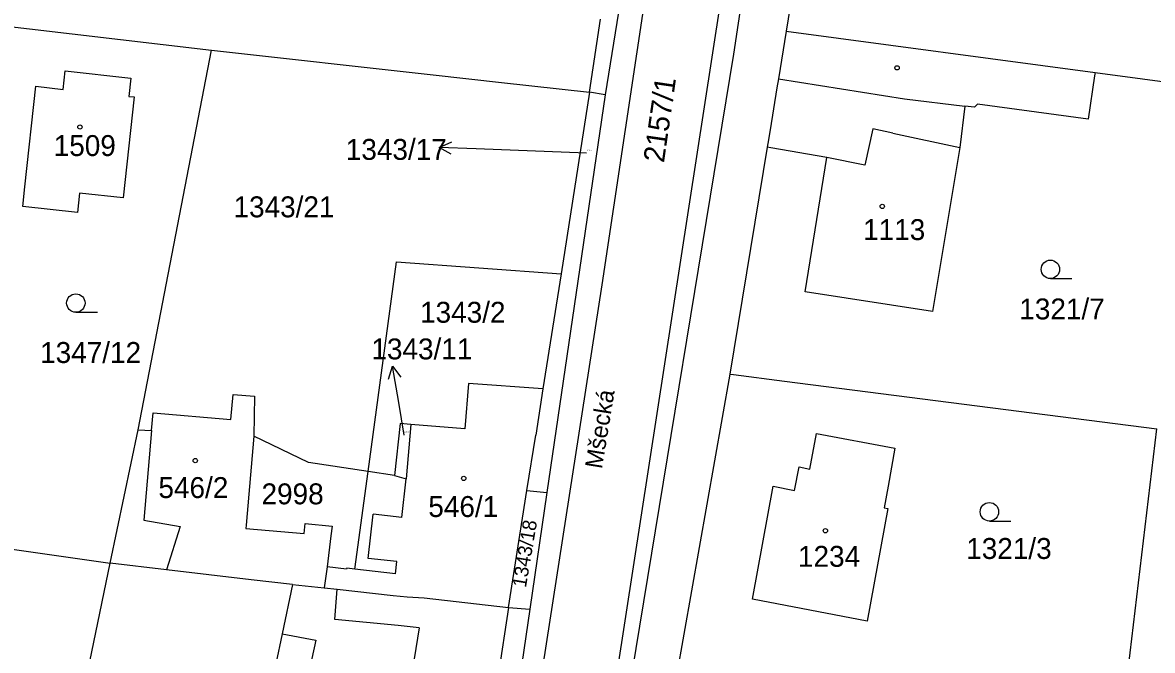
# Model space of a CAD drawing. Extents: x -779596 to -776743, y -1030330 to -1024513.
# Drawn here: x -778783.4 to -778691.5, y -1030030.7 to -1029979.6 of the extents above; entities that cross this region are included whole.
import ezdxf

# ---------------------------------------------------------------- set-up
doc = ezdxf.new("R2010")
doc.units = 0
for name, color, linetype in [('hranice parcel', 7, 'Continuous'), ('hranice vnitřní', 7, 'Continuous'), ('kultura', 7, 'Continuous'), ('názvosloví', 7, 'Continuous'), ('č_ parcel šipka', 7, 'Continuous'), ('č_pacel stav_', 7, 'Continuous'), ('č_parcel poz_', 7, 'Continuous')]:
    doc.layers.add(name, color=color, linetype=linetype)

msp = doc.modelspace()

# ---------------------------------------------------------------- linework, layer by layer
at = {"layer": 'hranice parcel'}
for points in [[(-778725.53, -1029982.22), (-778718.49, -1029935.38)], [(-778728.73, -1029940.47), (-778736.01, -1029985.51)], [(-778716.73, -1029952.26), (-778721.27, -1029980.34)], [(-778786.82, -1029979.69), (-778768.04, -1029981.88)], [(-778737.27, -1029985.31), (-778736.38, -1029979.37)], [(-778721.27, -1029980.34), (-778721.91, -1029984.21)], [(-778721.27, -1029980.34), (-778696.14, -1029983.71)], [(-778774.01, -1030012.75), (-778768.04, -1029981.88)], [(-778768.04, -1029981.88), (-778750, -1029983.89)], [(-778733.8, -1030032.5), (-778725.53, -1029982.22)], [(-778780.1, -1029985.07), (-778779.94, -1029983.57)], [(-778779.94, -1029983.57), (-778774.6, -1029984.15)], [(-778774.6, -1029984.15), (-778774.76, -1029985.65)], [(-778750, -1029983.89), (-778744.45, -1029984.51)], [(-778721.91, -1029984.21), (-778722.03, -1029984.94)], [(-778696.18, -1029983.97), (-778696.71, -1029987.5)], [(-778696.14, -1029983.71), (-778696.18, -1029983.97)], [(-778696.14, -1029983.71), (-778688.44, -1029984.74)], [(-778783.23, -1029992.99), (-778782.34, -1029984.82)], [(-778782.34, -1029984.82), (-778780.1, -1029985.07)], [(-778744.45, -1029984.51), (-778737.27, -1029985.31)], [(-778737.27, -1029985.31), (-778739.6, -1030000.07)], [(-778736.01, -1029985.51), (-778737.27, -1029985.31)], [(-778722.03, -1029984.94), (-778722.59, -1029988.37)], [(-778774.33, -1029985.69), (-778775.22, -1029993.9)], [(-778774.76, -1029985.65), (-778774.33, -1029985.69)], [(-778736.01, -1029985.51), (-778740.75, -1030017.85)], [(-778705.71, -1029986.27), (-778705.95, -1029986.52)], [(-778696.71, -1029987.5), (-778705.71, -1029986.27)], [(-778706.74, -1029986.43), (-778707.14, -1029989.8)], [(-778705.95, -1029986.52), (-778706.74, -1029986.43)], [(-778722.59, -1029988.37), (-778722.77, -1029989.46)], [(-778722.83, -1029989.78), (-778725.86, -1030008.21)], [(-778722.77, -1029989.46), (-778722.83, -1029989.78)], [(-778722.53, -1029989.83), (-778722.83, -1029989.78)], [(-778717.97, -1029990.6), (-778722.53, -1029989.83)], [(-778707.14, -1029989.8), (-778709.38, -1030003.12)], [(-778719.73, -1030001.54), (-778717.97, -1029990.6)], [(-778783.4, -1029994.58), (-778783.23, -1029992.99)], [(-778778.77, -1029993.52), (-778778.94, -1029995.07)], [(-778775.22, -1029993.9), (-778778.77, -1029993.52)], [(-778778.94, -1029995.07), (-778783.4, -1029994.58)], [(-778755.3, -1030016.13), (-778753, -1029999.1)], [(-778753, -1029999.1), (-778739.6, -1030000.07)], [(-778739.6, -1030000.07), (-778741.07, -1030009.42)], [(-778709.38, -1030003.12), (-778719.73, -1030001.54)], [(-778725.86, -1030008.21), (-778730.22, -1030032.87)], [(-778725.86, -1030008.21), (-778725.56, -1030008.25)], [(-778725.56, -1030008.25), (-778721.41, -1030008.78)], [(-778747.12, -1030008.99), (-778747.44, -1030012.67)], [(-778741.07, -1030009.42), (-778747.12, -1030008.99)], [(-778721.41, -1030008.78), (-778691.13, -1030012.66)], [(-778766.47, -1030011.91), (-778766.29, -1030009.87)], [(-778766.29, -1030009.87), (-778764.55, -1030010.02)], [(-778764.55, -1030010.02), (-778764.6, -1030013.27)], [(-778741.07, -1030009.42), (-778741.66, -1030013.17)], [(-778772.91, -1030012.81), (-778772.79, -1030011.37)], [(-778772.79, -1030011.37), (-778766.47, -1030011.91)], [(-778776.28, -1030023.59), (-778774.01, -1030012.75)], [(-778774.01, -1030012.75), (-778772.91, -1030012.81)], [(-778752.7, -1030012.22), (-778753.15, -1030016.46)], [(-778751.82, -1030012.3), (-778752.7, -1030012.22)], [(-778751.82, -1030012.3), (-778752.21, -1030016.73)], [(-778747.44, -1030012.67), (-778751.82, -1030012.3)], [(-778693.98, -1030036.57), (-778691.13, -1030012.66)], [(-778764.6, -1030013.27), (-778765.23, -1030020.49)], [(-778760.14, -1030015.4), (-778764.6, -1030013.27)], [(-778742.39, -1030017.69), (-778741.66, -1030013.17)], [(-778719.35, -1030015.93), (-778718.81, -1030013.05)], [(-778718.81, -1030013.05), (-778712.45, -1030014.24)], [(-778712.45, -1030014.24), (-778712.99, -1030017.33)], [(-778755.3, -1030016.13), (-778760.14, -1030015.4)], [(-778756.38, -1030024.07), (-778755.3, -1030016.13)], [(-778753.15, -1030016.46), (-778755.3, -1030016.13)], [(-778753.15, -1030016.46), (-778752.21, -1030016.73)], [(-778720.59, -1030017.67), (-778720.23, -1030015.76)], [(-778720.23, -1030015.76), (-778719.35, -1030015.93)], [(-778724.01, -1030026.52), (-778722.35, -1030017.33)], [(-778722.35, -1030017.33), (-778720.59, -1030017.67)], [(-778712.99, -1030017.33), (-778713.3, -1030019.08)], [(-778743.88, -1030027.2), (-778742.39, -1030017.69)], [(-778742.39, -1030017.69), (-778740.75, -1030017.85)], [(-778740.75, -1030017.85), (-778742.14, -1030027.32)], [(-778713, -1030019.14), (-778714.68, -1030028.29)], [(-778713.3, -1030019.08), (-778713, -1030019.14)], [(-778795.65, -1030020.83), (-778776.28, -1030023.59)], [(-778765.23, -1030020.49), (-778765.25, -1030020.77)], [(-778765.25, -1030020.77), (-778760.49, -1030021.18)], [(-778760.49, -1030021.18), (-778760.41, -1030020.36)], [(-778760.41, -1030020.36), (-778758.21, -1030020.57)], [(-778758.21, -1030020.57), (-778758.32, -1030021.37)], [(-778758.32, -1030021.37), (-778758.64, -1030023.89)], [(-778778.77, -1030035.63), (-778776.28, -1030023.59)], [(-778771.71, -1030024.12), (-778776.28, -1030023.59)], [(-778758.64, -1030023.89), (-778758.86, -1030025.6)], [(-778757.05, -1030024.07), (-778758.64, -1030023.89)], [(-778764.82, -1030024.93), (-778771.71, -1030024.12)], [(-778757.04, -1030024), (-778757.05, -1030024.07)], [(-778756.38, -1030024.07), (-778757.04, -1030024)], [(-778761.45, -1030025.32), (-778764.82, -1030024.93)], [(-778761.45, -1030025.32), (-778762.3, -1030029.32)], [(-778761.45, -1030025.32), (-778758.86, -1030025.6)], [(-778758.86, -1030025.6), (-778757.81, -1030025.71)], [(-778757.81, -1030025.71), (-778753.25, -1030026.2)], [(-778753.25, -1030026.2), (-778752.13, -1030026.32)], [(-778752.13, -1030026.32), (-778750.73, -1030026.41)], [(-778750.73, -1030026.41), (-778743.88, -1030027.2)], [(-778714.68, -1030028.29), (-778724.01, -1030026.52)], [(-778742.14, -1030027.32), (-778747.97, -1030067.13)], [(-778743.88, -1030027.2), (-778745.55, -1030038.23)], [(-778743.88, -1030027.2), (-778742.14, -1030027.32)], [(-778762.3, -1030029.32), (-778763.33, -1030034.2)]]:
    msp.add_lwpolyline(points, dxfattribs=at)
at = {"layer": 'hranice vnitřní'}
for points in [[(-778716.35, -1029911.33), (-778735.03, -1030032.31)], [(-778736.26, -1030000.97), (-778729.52, -1029956.19)], [(-778721.91, -1029984.21), (-778711.65, -1029985.85)], [(-778711.65, -1029985.85), (-778706.74, -1029986.43)], [(-778714.24, -1029988.28), (-778714.87, -1029991.22)], [(-778712.61, -1029988.63), (-778714.24, -1029988.28)], [(-778712.61, -1029988.63), (-778707.14, -1029989.8)], [(-778714.87, -1029991.22), (-778717.97, -1029990.6)], [(-778742.1, -1030038.71), (-778736.26, -1030000.97)], [(-778772.91, -1030012.81), (-778773.54, -1030020.09)], [(-778752.55, -1030019.86), (-778752.21, -1030016.73)], [(-778773.54, -1030020.09), (-778770.58, -1030020.6)], [(-778755.28, -1030023.2), (-778754.89, -1030019.6)], [(-778752.55, -1030019.86), (-778754.89, -1030019.6)], [(-778770.58, -1030020.6), (-778771.71, -1030024.12)], [(-778752.95, -1030023.46), (-778755.28, -1030023.2)], [(-778753.06, -1030024.44), (-778752.95, -1030023.46)], [(-778753.06, -1030024.44), (-778756.38, -1030024.07)], [(-778758.01, -1030028.16), (-778757.81, -1030025.71)], [(-778752.86, -1030028.66), (-778758.01, -1030028.16)], [(-778762.3, -1030029.32), (-778759.55, -1030029.85)], [(-778751.13, -1030028.83), (-778752.86, -1030028.66)], [(-778751.13, -1030028.83), (-778752.86, -1030039.44)], [(-778759.55, -1030029.85), (-778760.64, -1030034.79)]]:
    msp.add_lwpolyline(points, dxfattribs=at)
at = {"layer": 'kultura'}
for points in [[(-778699.78, -1030000.45), (-778698.03, -1030000.45)], [(-778779.08, -1030003.19), (-778777.33, -1030003.19)], [(-778704.74, -1030020.16), (-778702.99, -1030020.16)]]:
    msp.add_lwpolyline(points, dxfattribs=at)
for centre, radius in [((-778712.26, -1029983.32), 0.175), ((-778778.75, -1029988.13), 0.175), ((-778713.46, -1029994.58), 0.175), ((-778699.78, -1029999.7), 0.75), ((-778779.08, -1030002.44), 0.75), ((-778769.36, -1030015.24), 0.175), ((-778747.52, -1030016.69), 0.175), ((-778704.74, -1030019.41), 0.75), ((-778718.09, -1030020.95), 0.175)]:
    msp.add_circle(centre, radius, dxfattribs=at)
at = {"layer": 'č_ parcel šipka'}
for points in [[(-778748.528, -1029990.329), (-778749.507, -1029989.79), (-778748.488, -1029989.331)], [(-778746.51, -1029989.91), (-778749.507, -1029989.79)], [(-778737.52, -1029990.26), (-778746.51, -1029989.91)], [(-778753.633, -1030008.64), (-778753.305, -1030007.572), (-778752.647, -1030008.475)], [(-778752.81, -1030010.53), (-778753.305, -1030007.572)], [(-778752.37, -1030013.18), (-778752.81, -1030010.53)]]:
    msp.add_lwpolyline(points, dxfattribs=at)

# ---------------------------------------------------------------- texts
at = {"layer": 'názvosloví'}
msp.add_text('Mšecká', height=1.4, rotation=80.70064, dxfattribs=at).set_placement((-778736.275, -1030015.971))
at = {"layer": 'č_ parcel šipka'}
for s, p in [('1343/17', (-778757.113, -1029990.8)), ('1343/11', (-778755.03, -1030007.02))]:
    msp.add_text(s, height=1.7, dxfattribs=at).set_placement(p)
at = {"layer": 'č_pacel stav_'}
for s, p in [('1509', (-778780.88, -1029990.49)), ('1113', (-778715.02, -1029997.32)), ('546/2', (-778772.36, -1030018.29)), ('546/1', (-778750.4, -1030019.83)), ('1234', (-778720.32, -1030023.88))]:
    msp.add_text(s, height=1.7, dxfattribs=at).set_placement(p)
at = {"layer": 'č_parcel poz_'}
for s, height, rotation, p in [('2157/1', 1.7, 81.80065, (-778731.229, -1029991.084)), ('1343/18', 1.14, 80.40064, (-778742.457, -1030025.61))]:
    msp.add_text(s, height=height, rotation=rotation, dxfattribs=at).set_placement(p)
for s, height, p in [('1343/17', 0.1, (-778737.553, -1029990.06)), ('1343/21', 1.7, (-778766.25, -1029995.47)), ('1343/2', 1.7, (-778751.07, -1030004.04)), ('1321/7', 1.7, (-778702.31, -1030003.77)), ('1347/12', 1.7, (-778781.986, -1030007.31)), ('1343/11', 0.1, (-778752.403, -1030012.98)), ('2998', 1.7, (-778763.97, -1030018.8)), ('1321/3', 1.7, (-778706.63, -1030023.24))]:
    msp.add_text(s, height=height, dxfattribs=at).set_placement(p)

doc.saveas('drawing.dxf')
